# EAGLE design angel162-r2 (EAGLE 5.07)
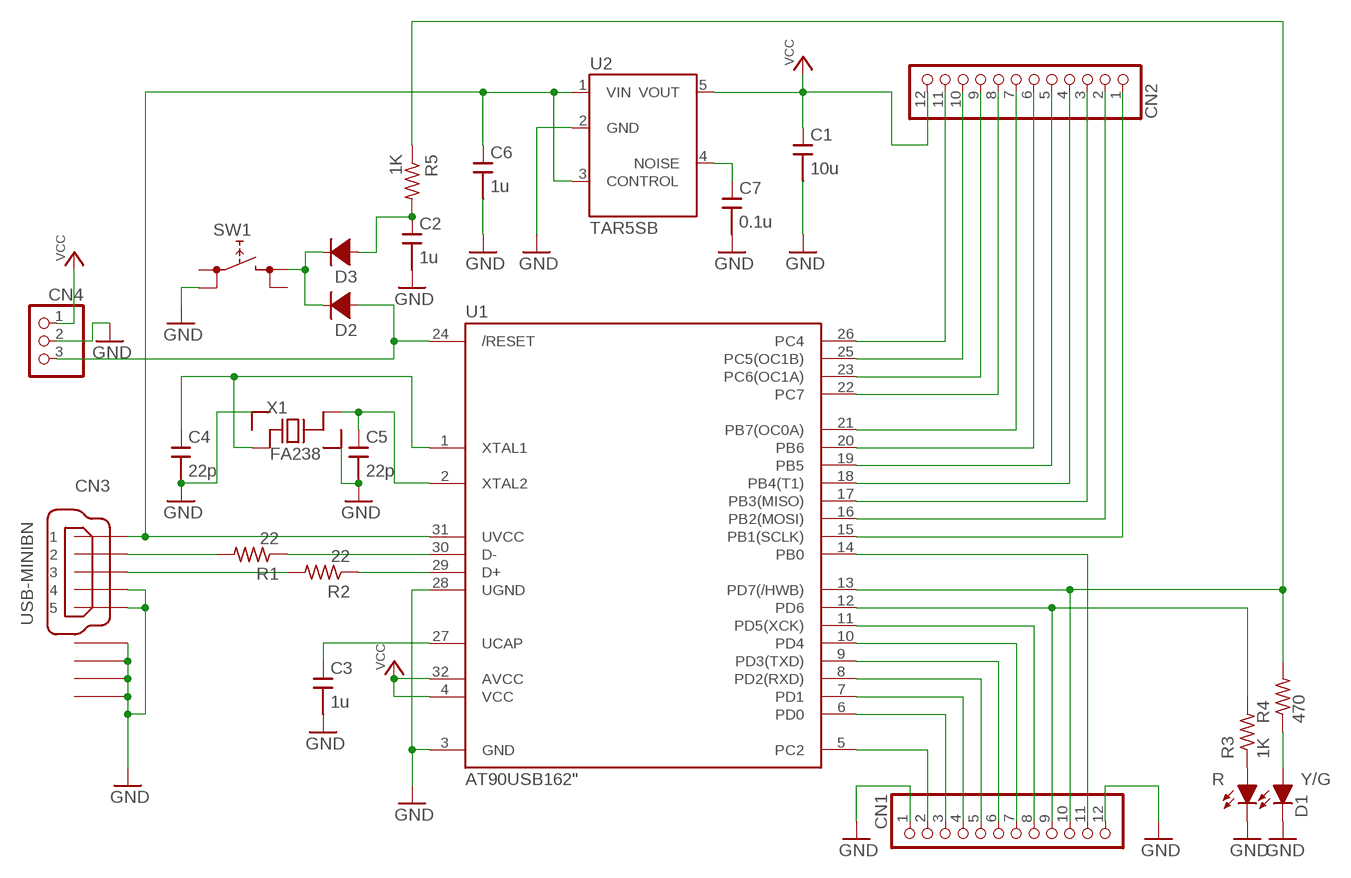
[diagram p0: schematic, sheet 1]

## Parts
C1  10u  C/SMDC2012  [C2012]
C2  1u  C/SMDC1608  [C1608]
C3  1u  C/SMDC1608  [C1608]
C4  22p  C/SMDC3216  [C3216]
C5  22p  C/SMDC3216  [C3216]
C6  1u  C/SMDC1608  [C1608]
C7  0.1u  C/SMDC2012  [C2012]
CN1  PINHDR12  [PINHDRX12]
CN2  PINHDR12  [PINHDRX12]
CN3  USB-MINIBN  [USB-MINIB-N]
CN4  PINHDR3  [PINHDR1X3]
D1  SEC2XX4  [LED3025]
D2  D/SMD2012  [D2012]
D3  D/SMD2012  [D2012]
R1  22  R/SMDR2012  [R2012]
R2  22  R/SMDR2012  [R2012]
R3  1K  R/SMDR2012  [R2012]
R4  470  R/SMDR2012  [R2012]
R5  1K  R/SMDR2012  [R2012]
SW1  TACTSWTACTSW/SMD  [TACTSW/SMD]
U1  AT90USB162"  [TQFP32]
U2  TAR5SB  [SOT235]
X1  FA238  [FA238]

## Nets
GND [Power]: C1.2 C2.2 C3.2 C4.2 C5.2 C6.2 C7.2 CN1.1 CN1.12 CN3.4 CN3.5 CN3.M1(GND) CN3.M2(GND) CN3.M3(GND) CN3.M4(GND) CN4.2 D1.1(C0) D1.2(C1) SW1.2 U1.3(GND) U1.28(UGND) U2.2(GND) X1.2 X1.4
N$1: CN1.2 U1.5(PC2)
N$2: CN1.3 U1.6(PD0)
N$3: CN1.4 U1.7(PD1)
N$4: CN1.5 U1.8(PD2(RXD))
N$7: CN1.6 U1.9(PD3(TXD))
N$8: CN1.7 U1.10(PD4)
N$9: CN1.8 U1.11(PD5(XCK))
N$10: CN1.9 R3.2 U1.12(PD6)
N$11: CN1.10 R4.2 R5.1 U1.13(PD7(/HWB))
N$12: CN1.11 U1.14(PB0)
N$13 [Power]: C3.1 U1.27(UCAP)
N$14: CN2.11 U1.26(PC4)
N$15: CN2.10 U1.25(PC5(OC1B))
N$16: CN2.9 U1.23(PC6(OC1A))
N$17: CN2.8 U1.22(PC7)
N$19: CN3.2 R1.2
N$20: CN2.7 U1.21(PB7(OC0A))
N$21: CN2.6 U1.20(PB6)
N$22: CN2.5 U1.19(PB5)
N$23: D1.3(A1) R3.1
N$24: D1.4(A0) R4.1
N$25: R1.1 U1.30(D-)
N$26: CN2.4 U1.18(PB4(T1))
N$27: C4.1 U1.1(XTAL1) X1.1
N$28: C5.1 U1.2(XTAL2) X1.3
N$29: C7.1 U2.4(NOISE)
N$30 [Power]: C6.1 CN3.1 U1.31(UVCC) U2.1(VIN) U2.3(CONTROL)
N$31: CN2.3 U1.17(PB3(MISO))
N$32: CN2.2 U1.16(PB2(MOSI))
N$33: CN2.1 U1.15(PB1(SCLK))
N$34: CN3.3 R2.2
N$35: R2.1 U1.29(D+)
N$36: D2.2(C) D3.2(C) SW1.3
N$38: CN4.3 D2.1(A) U1.24(/RESET)
N$39: C2.1 D3.1(A) R5.2
VCC [Power]: C1.1 CN2.12 CN4.1 U1.4(VCC) U1.32(AVCC) U2.5(VOUT)
Unconnected: SW1.1 SW1.4

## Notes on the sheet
- R | Y/G

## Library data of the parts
C1-C7 = SRT162-010:C/SMD
CN1 CN2 = SRT162-010:PINHDR12
CN3 = SRT162-010:USB-MINIB
CN4 = SRT162-010:PINHDR3
D1 = SRT162-010:SEC2XX4
D2 D3 = SRT162-010:D/SMD
R1-R5 = SRT162-010:R/SMD
SW1 = SRT162-010:TACTSW: 4pin tactsw (1,2 - 3,4)
U1 = SRT162-010:AT90USB162: AT90USB162 Atmel AVR
U2 = SRT162-010:TAR5SB
X1 = SRT162-010:FA238

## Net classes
1 Power: width 0.406 mm, clearance 0.203 mm to class 0

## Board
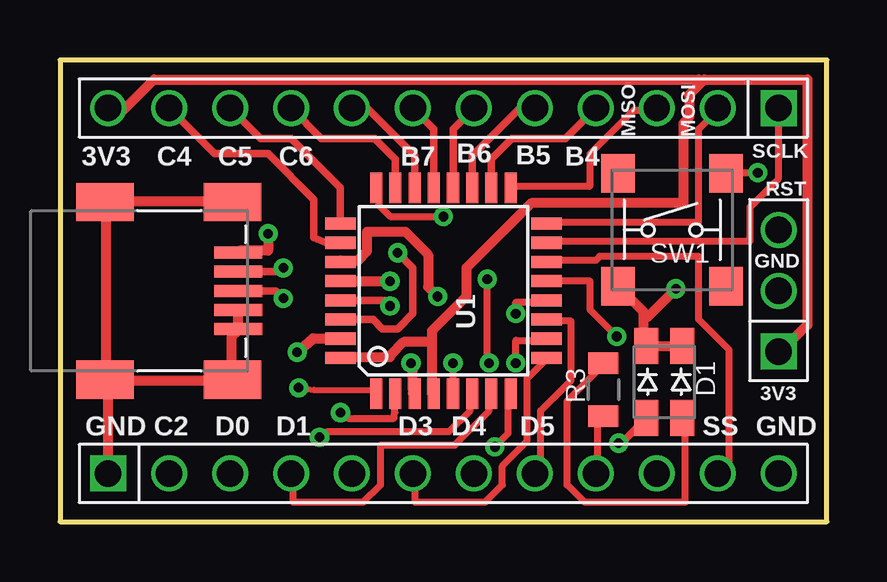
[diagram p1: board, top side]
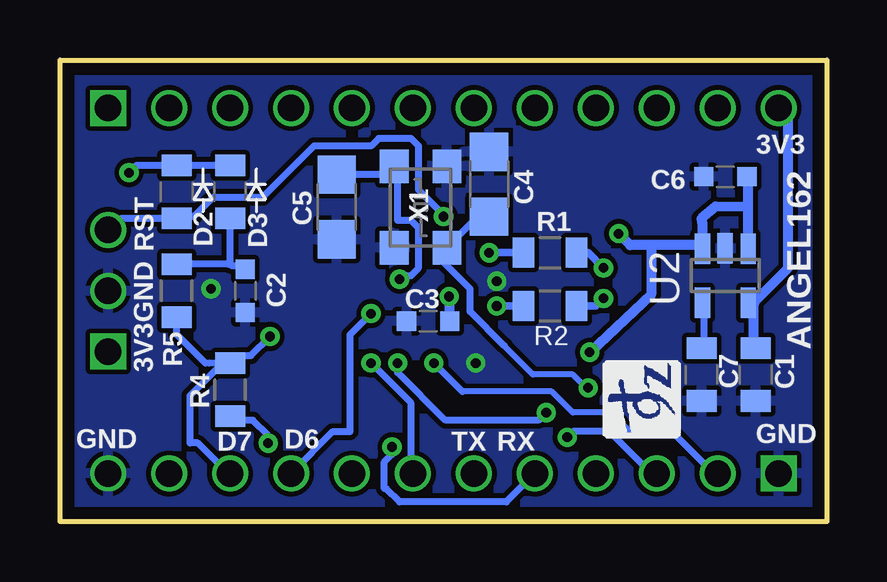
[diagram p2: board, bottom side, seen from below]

Size 31.95 x 19.25 mm. Coordinates in mm from the lower left corner, seen from the top.
Outline: 0,0 31.95,0 31.95,19.25 0,19.25 0,0
Copper layers (1*16): Top 0.0356mm / dielectric 1.5011mm / Bottom 0.0356mm
Design rules "ezpcb-suz": minimum track width 0.3mm, minimum drill 0.4mm, track to track 0.2mm, track to pad 0.235mm, pad to pad 0.2mm, via to via 0.2mm, smd to smd 0.2mm, copper to edge 0.5mm, drill to drill 0.45mm, minimum pad ring 0.2mm, minimum via ring 0.2mm, stop-mask expansion 4mil, vias tented up to drill 0mil, thermal gap 0.2mm
vRestrict: area 20.1,6.4 to 21.4,12.8; area 12.8,14.4 to 19.2,15.7; area 12.8,3.6 to 19.2,4.9; area 0.4,18.2 to 31.5,18.8; area 0.4,0.4 to 31.5,1.1; area 31.2,0.4 to 31.8,18.8

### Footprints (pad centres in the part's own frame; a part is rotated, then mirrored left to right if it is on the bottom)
C2012 = smd 0.9 x 1.25: 1 -1.1,0; 2 1.1,0
C1608 = smd 0.8 x 0.8: 1 -0.9,0; 2 0.9,0
C3216 = smd 1.6 x 1.6: 1 -1.35,0; 2 1.35,0
PINHDRX12 = drill 1.1 square: 1 -13.97,0 | drill 1.1 round: 2 -11.43,0; 3 -8.89,0; 4 -6.35,0; 5 -3.81,0; 6 -1.27,0; 7 1.27,0; 8 3.81,0; 9 6.35,0; 10 8.89,0; 11 11.43,0; 12 13.97,0
USB-MINIB-N = smd 2 x 0.5: 1 3.52,1.6; 2 3.52,0.8; 3 3.52,0; 4 3.52,-0.8; 5 3.52,-1.6 | smd 2.4 x 1.6: M1 -2.03,-3.7; M2 -2.03,3.7; M3 3.27,3.7; M4 3.27,-3.7
PINHDR1X3 = drill 1.1 square: 1 -2.54,0 | drill 1.1 round: 2 0,0; 3 2.54,0
LED3025 = smd 1.5 x 1: 1 1.5,0.75; 2 1.5,-0.75; 3 -1.5,-0.75; 4 -1.5,0.75
D2012 = smd 0.9 x 1.25: 1 -1.1,0; 2 1.1,0
R2012 = smd 0.9 x 1.25: 1 -1.1,0; 2 1.1,0
TACTSW/SMD = smd 1.4 x 1.6: 1 -2.25,2.35; 2 -2.25,-2.35; 3 2.25,2.35; 4 2.25,-2.35
TQFP32 = smd 1.27 x 0.508: 1 -4.293,2.8; 2 -4.293,2; 3 -4.293,1.2; 4 -4.293,0.4; 5 -4.293,-0.4; 6 -4.293,-1.2; 7 -4.293,-2; 8 -4.293,-2.8; 17 4.293,-2.8; 18 4.293,-2; 19 4.293,-1.2; 20 4.293,-0.4; 21 4.293,0.4; 22 4.293,1.2; 23 4.293,2; 24 4.293,2.8 | smd 0.508 x 1.27: 9 -2.8,-4.293; 10 -2,-4.293; 11 -1.2,-4.293; 12 -0.4,-4.293; 13 0.4,-4.293; 14 1.2,-4.293; 15 2,-4.293; 16 2.8,-4.293; 25 2.8,4.293; 26 2,4.293; 27 1.2,4.293; 28 0.4,4.293; 29 -0.4,4.293; 30 -1.2,4.293; 31 -2,4.293; 32 -2.8,4.293
SOT235 = smd 0.635 x 1.27: 1 -0.95,-1.125; 2 0.013,-1.135; 3 0.95,-1.125; 4 0.95,1.125; 5 -0.95,1.125
FA238 = smd 1.4 x 1.2: 1 -1.7,-1.1; 2 1.7,-1.1; 3 1.7,1.1; 4 -1.7,1.1

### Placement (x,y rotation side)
C1  2.96,6.13 270 bottom
C2  24.23,9.62 270 bottom
C3  16.61,8.36 180 bottom
C4  14.07,14.07 90 bottom
C5  20.42,13.12 270 bottom
C6  4.23,14.39 180 bottom
C7  5.22,6.13 270 bottom
CN1  15.98,2 0 top
CN2  15.98,17.25 180 top
CN3  3.91,9.62 0 top
CN4  29.95,9.62 90 top
D1  25.18,5.81 90 top
D2  27.09,13.75 90 bottom
D3  24.87,13.75 90 bottom
R1  11.53,11.21 0 bottom
R2  11.53,8.99 0 bottom
R3  22.64,5.5 270 top
R4  24.87,5.5 90 bottom
R5  27.09,9.62 90 bottom
SW1  25.5,12.16 0 top
U1  15.98,9.62 90 top
U2  4.23,10.26 180 bottom
X1  16.93,13.12 90 bottom

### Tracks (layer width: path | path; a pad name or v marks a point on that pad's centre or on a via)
GND  (via drill 0.4)
  Top 0.406: CN3.4 CN3.5 7.32,7.88 7.16,7.72 7.16,6.13 CN3.M4 | 14.71,5.34 U1.3 14.71,5.5 14.71,6.53 v14.63,6.61 | CN3.M4 7.24,5.89 | CN3.M3 7.16,13.36 1.93,13.36 CN3.M2 1.93,13.12 1.93,6.13 CN3.M1 | v13.75,10.02 U1.28 | D1.2 25.9,7.32 24.47,7.32 D1.1 24.31,7.48 24.31,8.51 | 24.31,8.51 24.31,8.75 23.28,9.78 SW1.2 | v25.66,9.7 24.47,8.51 24.31,8.51 | CN1.1 2,5.81 1.93,5.89 CN3.M1 | CN1.1 | CN3.M4 7.01,5.89 2.16,5.89 CN3.M1
  pour Bottom: -0.14,19.73 32.48,19.79 32.48,-0.54 -0.46,-0.59
N$1  (via drill 0.4)
  Top 0.3: v16.37,6.61 U1.5
  Bottom 0.254: 6.37,3.67 8.12,3.67 8.99,4.54 10.58,4.54 11.45,5.42 15.18,5.42
  Bottom 0.3: 15.18,5.42 v16.37,6.61 | 6.37,3.67 4.7,2 CN1.2
N$2  (via drill 0.4)
  Top 0.3: v10.82,3.51 11.13,3.75 16.21,3.75 17.09,4.62 17.09,5.18 17.17,5.26 U1.6
  Bottom 0.3: v10.82,3.51 10.58,3.75 9.07,3.75 7.32,2 CN1.3
N$3
  Top 0.3: U1.7 17.96,5.26 17.88,5.18 17.88,4.62 16.45,3.2 13.36,3.2 13.36,1.53 12.64,0.81 9.7,0.81 9.7,1.93 CN1.4
N$4  (via drill 0.4)
  Top 0.3: v18.12,3.12 18.67,3.67 18.67,5.18 18.75,5.26 U1.8
  Bottom 0.3: v18.12,3.12 18.12,2.8 18.44,2.48 18.44,1.37 18.36,1.37 17.8,0.81 13.36,0.81 CN1.5
N$7
  Top 0.3: U1.9 20.26,6.77 19.47,5.97 19.47,3.35 18.44,2.32 18.44,1.53 17.72,0.81 14.78,0.81 14.78,1.93 CN1.6
N$8  (via drill 0.4)
  Top 0.3: v18.99,6.61 18.99,7.56 20.26,7.56 U1.10
  Bottom 0.3: v18.99,6.61 17.32,4.94 17.32,2 CN1.7
N$9
  Top 0.3: U1.11 20.34,8.36 21.29,8.36 21.29,5.89 20.02,4.62 20.02,2.16 19.86,2 CN1.8
N$10  (via drill 0.4)
  Top 0.3: R3.2 22.4,4.15 22.4,2 CN1.9 | v18.99,8.67 18.99,9.15 20.26,9.15 U1.12
  Bottom 0.3: v18.99,8.67 19.86,7.8 19.86,3.75 20.58,3.75 CN1.9 | CN1.9
N$11  (via drill 0.4)
  Top 0.3: v23.2,7.72 22.09,8.83 22.09,10.02 20.34,10.02 U1.13
  Bottom 0.3: R4.2 25.9,6.61 25.98,6.69 27.01,7.72 27.09,7.8 27.09,8.51 R5.1 | R4.2 25.74,6.61 | R4.2 25.26,6.53 | R4.2 24.79,6.69 24.55,6.93 23.99,6.93 v23.2,7.72 | R4.2 25.34,6.45 26.53,5.26 26.53,3.27 26.21,3.27 24.94,2 CN1.10
N$12
  Top 0.3: U1.14 20.34,10.89 22.33,10.89 22.48,11.05 26.61,11.05 26.61,8.43 27.88,7.16 27.88,2.4 27.48,2 CN1.11
N$13  (via drill 0.4)
  Top 0.406: v15.74,9.39 15.34,9.78 15.34,11.13 14.39,12.09 12.8,12.09 12.8,11.29 12.4,10.89 11.69,10.89 U1.27
  Bottom 0.406: v15.74,9.39 15.74,8.36 C3.1
N$14
  Top 0.305: U1.26 11.12,11.62 10.58,11.85 10.58,13.44 8.67,15.34 6.45,15.34 CN2.11
N$15
  Top 0.305: U1.25 11.68,13.92 9.62,15.98 8.36,15.98 CN2.10
N$16
  Top 0.305: U1.23 13.98,15.12 13.12,15.98 10.89,15.98 CN2.9
N$17
  Top 0.305: U1.22 14.78,15.27 12.8,17.25 CN2.8
N$19  (via drill 0.4)
  Top 0.305: CN3.2 9.16,10.43 v9.31,10.58
  Bottom 0.305: v9.31,10.58 9.94,11.21 R1.2
N$20
  Top 0.305: U1.21 15.58,16.38 CN2.7
N$21
  Top 0.305: U1.20 16.38,16.38 CN2.6
N$22
  Top 0.305: U1.19 17.18,15.27 19.15,17.25 CN2.5
N$23
  Top 0.3: R3.1 22.64,6.53 21.13,5.02 21.13,1.53 21.85,0.81 26.06,0.81 26.06,4.23 25.98,4.31 D1.3
N$24  (via drill 0.4)
  Top 0.305: v23.28,3.27 23.6,3.48 D1.4
  Bottom 0.3: v23.28,3.27 23.28,3.59 23.91,4.23 24.71,4.23 R4.1 | v23.28,3.27
N$25  (via drill 0.4)
  Top 0.305: U1.30 13.05,8.43 13.44,8.04 14.07,8.04 14.71,8.67 14.71,10.58 v14.07,11.21
  Bottom 0.305: v14.07,11.21 R1.1
N$26
  Top 0.305: U1.18 17.98,15.12 18.83,15.98 21.05,15.98 CN2.4
N$27  (via drill 0.4)
  Top 0.254: 13.12,5.34 12.96,5.5 10.58,5.5 10.02,5.58 v9.94,5.58
  Top 0.3: 13.12,5.34 U1.1
  Bottom 0.254: 13.44,7.32 12.24,6.13 10.58,6.13 10.02,5.58 v9.94,5.58
  Bottom 0.3: 15.74,11.53 15.82,11.45 | 15.74,11.53 14.63,12.64 14.15,12.64 C4.1 | 15.74,11.53 | 15.74,11.53 X1.1 15.9,11.29 15.98,11.29 15.98,10.82 14.86,9.7 14.86,8.75 13.44,7.32
N$28  (via drill 0.4)
  Top 0.3: v11.69,4.54 12.01,4.31 13.91,4.31 13.96,4.54 13.96,5.18 13.91,5.26 U1.2 | v17.88,6.61 17.8,6.69 v17.8,10.1
  Bottom 0.3: v11.69,4.54 12.01,4.23 15.9,4.23 17.88,6.21 v17.88,6.61 | v17.8,10.1 17.72,10.1 17.56,10.26 17.32,10.26 17.01,10.58 17.01,12.24 17.32,12.56 17.88,12.56 17.88,14.15 18.28,14.55 18.04,14.78 18.04,14.86 X1.3 18.36,14.47 C5.1 | C5.1
N$29
  Bottom 0.3: C7.1 5.5,7.24 5.1,7.64 5.1,9.07 U2.4
N$30  (via drill 0.4)
  Top 0.406: v8.67,12.01 8.67,11.29 7.48,11.29 CN3.1 | v9.88,7.06 10.54,7.64 11.61,7.64 U1.31
  Bottom 0.406: 3.28,13.12 3.28,11.45 U2.1 | 3.28,13.12 3.28,14.31 C6.1 | 3.28,13.12 4.63,13.14 5.22,12.63 5.18,12.4 5.18,11.45 U2.3 5.34,11.53 7.32,11.53 | v8.67,12.01 8.2,11.53 7.32,11.53 | v9.88,7.06 7.32,9.47 7.32,11.53
N$31
  Top 0.3: U1.17 18.83,13.99 22.09,13.99 22.09,15.34 23.91,17.17 24.87,17.17 CN2.3
N$32
  Top 0.3: U1.16 20.34,12.48 26.61,12.48 26.61,16.37 27.41,17.17 CN2.2
N$33
  Top 0.3: U1.15 20.34,11.69 28.75,11.69 28.75,13.12 29.95,14.31 29.95,17.17 CN2.1
N$34  (via drill 0.4)
  Top 0.305: CN3.3 8.99,9.62 v9.31,9.31
  Bottom 0.305: v9.31,9.31 9.62,8.99 R2.2
N$35  (via drill 0.4)
  Top 0.305: v13.75,8.99 13.52,9.22 U1.29
  Bottom 0.305: v13.75,8.99 R2.1
N$36  (via drill 0.4)
  Top 0.3: v29.07,14.55 27.8,14.55 SW1.3
  Bottom 0.3: D3.2 24.94,14.86 D2.2 27.17,14.86 28.75,14.86 v29.07,14.55
N$38  (via drill 0.4)
  Top 0.3: 13.12,13.99 U1.24 13.28,13.83 13.28,13.2 13.75,12.72 v15.98,12.72
  Bottom 0.3: CN4.3 29.87,12.16 29.39,12.64 27.17,12.64 D2.1 27.01,12.72 26.37,12.72 25.58,13.51 23.52,13.51 21.37,15.66 18.99,15.66 18.67,15.98 17.32,15.98 17.01,15.66 17.01,13.83 15.98,12.8 v15.98,12.72 | CN4.3
N$39
  Bottom 0.3: 24.87,10.82 24.87,10.74 24.79,10.66 24.39,10.66 24.31,10.58 C2.1 | 24.87,10.82 24.87,12.64 D3.1 | R5.2 27.09,10.74 24.94,10.74 24.87,10.82
VCC
  Top 0.406: 15.5,7.48 15.5,7.96 16.93,9.39 16.93,10.58 19.63,13.28 25.98,13.28 25.98,16.61 26.21,16.85 26.21,17.8 26.73,18.32 | 15.5,7.48 15.5,5.34 U1.4 | 26.73,18.32 26.85,18.44 31.14,18.44 31.14,8.2 30.02,7.08 CN4.1 | CN2.12 2.48,17.01 3.91,18.44 26.61,18.44 26.73,18.32 | U1.32 11.69,6.85 13.75,6.85 13.75,6.93 14.31,7.48 15.5,7.48
  Bottom 0.406: 3.04,9.07 3.04,7.24 C1.1 | 3.04,9.07 3.28,9.07 U2.5 | 3.04,9.07 2.96,9.23 1.61,10.58 1.61,17.17 2,17.17 CN2.12

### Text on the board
tPlace: MISO | MOSI | 3V3 | C4 | C5 | C6 | B7 | B6 | B5 | B4 | SCLK | RST | GND | 3V3 | GND | C2 | D0 | D1 | D3 | D4 | D5 | SS | GND
bPlace: 3V3 | ANGEL162 | RST | GND | 3V3 | GND | D6 | GND | RX | TX | D7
